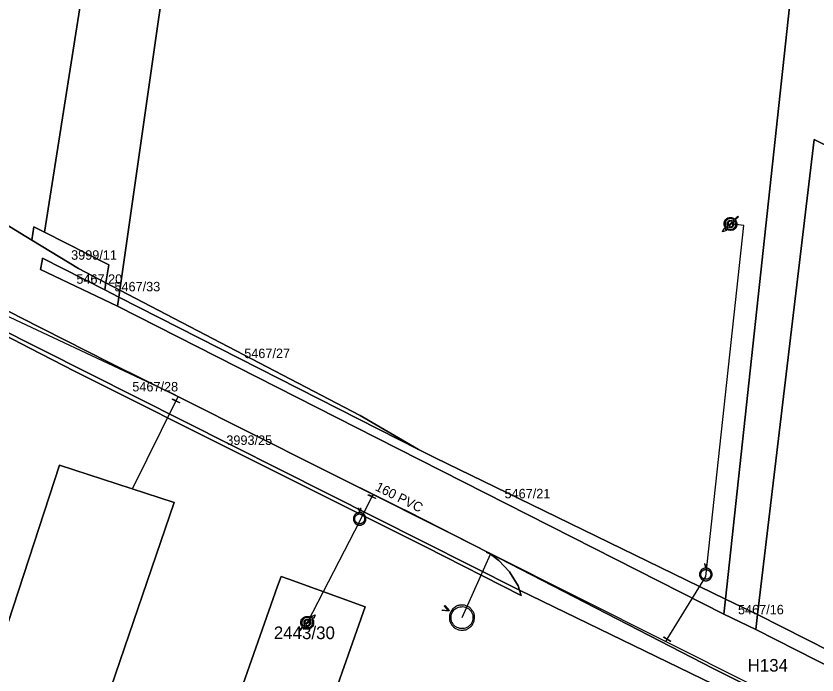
# Model space of a CAD drawing. Extents: x -570104 to -569328, y -1087857 to -1087418.
# Drawn here: x -569658.3 to -569531.5, y -1087675.5 to -1087571.3 of the extents above; entities that cross this region are included whole.
import ezdxf

# ---------------------------------------------------------------- set-up
doc = ezdxf.new("R2010")
doc.units = 0
for name, color, linetype in [('Adresní místo-text', 7, 'Continuous'), ('Armatura vodovodní', 7, 'Continuous'), ('Default', 7, 'Continuous'), ('Odběrné místo', 7, 'Continuous'), ('Označení hydrantu', 7, 'Continuous'), ('Parcela-polygon', 7, 'Continuous'), ('Parcela-text', 7, 'Continuous'), ('Vodovodní přípojka', 7, 'Continuous'), ('Vodovodní řad', 7, 'Continuous'), ('Vodovodní šachta', 7, 'Continuous'), ('Řad vodovodní popis', 7, 'Continuous')]:
    doc.layers.add(name, color=color, linetype=linetype)

msp = doc.modelspace()

# ---------------------------------------------------------------- linework, layer by layer
at = {"layer": 'Armatura vodovodní'}
for points in [[(-569632.42, -1087632.5), (-569633.54, -1087631.94), (-569633.51, -1087631.87), (-569632.39, -1087632.43), (-569632.42, -1087632.5)], [(-569601.42, -1087647.63), (-569602.54, -1087647.07), (-569602.51, -1087647), (-569601.39, -1087647.56), (-569601.42, -1087647.63)], [(-569583.78, -1087656.11), (-569582.64, -1087656.62), (-569582.67, -1087656.69), (-569583.81, -1087656.18), (-569583.78, -1087656.11)], [(-569555.75, -1087669.51), (-569554.69, -1087670.17), (-569554.73, -1087670.24), (-569555.79, -1087669.58), (-569555.75, -1087669.51)]]:
    msp.add_lwpolyline(points, dxfattribs=at)
at = {"layer": 'Default'}
for points, degree in [([(-569545.98, -1087604.85), (-569546.23, -1087604.57), (-569546.23, -1087604.19), (-569546.23, -1087603.77), (-569545.94, -1087603.48), (-569545.64, -1087603.18), (-569545.22, -1087603.18), (-569544.84, -1087603.18), (-569544.56, -1087603.43)], 3), ([(-569544.68, -1087603.55), (-569544.91, -1087603.35), (-569545.22, -1087603.35), (-569545.57, -1087603.35), (-569545.82, -1087603.6), (-569546.07, -1087603.84), (-569546.07, -1087604.19), (-569546.07, -1087604.5), (-569545.86, -1087604.73)], 3), ([(-569544.46, -1087603.54), (-569544.22, -1087603.81), (-569544.22, -1087604.19), (-569544.22, -1087604.61), (-569544.51, -1087604.9), (-569544.81, -1087605.2), (-569545.22, -1087605.2), (-569545.6, -1087605.2), (-569545.88, -1087604.96)], 3), ([(-569545.76, -1087604.84), (-569545.53, -1087605.03), (-569545.22, -1087605.03), (-569544.88, -1087605.03), (-569544.63, -1087604.78), (-569544.38, -1087604.54), (-569544.38, -1087604.19), (-569544.38, -1087603.88), (-569544.58, -1087603.66)], 3), ([(-569545.66, -1087604.52), (-569545.67, -1087604.5), (-569545.68, -1087604.48), (-569545.74, -1087604.35), (-569545.74, -1087604.19), (-569545.74, -1087604.03), (-569545.68, -1087603.9), (-569545.61, -1087603.77), (-569545.49, -1087603.7), (-569545.37, -1087603.63), (-569545.23, -1087603.63), (-569545.08, -1087603.63), (-569544.96, -1087603.71), (-569544.92, -1087603.73), (-569544.89, -1087603.76)], 3), ([(-569544.98, -1087603.85), (-569545.08, -1087603.76), (-569545.23, -1087603.76), (-569545.39, -1087603.76), (-569545.49, -1087603.87), (-569545.6, -1087603.98), (-569545.6, -1087604.19), (-569545.6, -1087604.32), (-569545.55, -1087604.42), (-569545.55, -1087604.42), (-569545.55, -1087604.42)], 3), ([(-569544.79, -1087603.88), (-569544.79, -1087603.89), (-569544.78, -1087603.91), (-569544.72, -1087604.04), (-569544.72, -1087604.18), (-569544.72, -1087604.44), (-569544.86, -1087604.6), (-569545, -1087604.75), (-569545.23, -1087604.75), (-569545.38, -1087604.75), (-569545.5, -1087604.68), (-569545.53, -1087604.66), (-569545.55, -1087604.64)], 3), ([(-569545.46, -1087604.54), (-569545.44, -1087604.56), (-569545.42, -1087604.57), (-569545.34, -1087604.62), (-569545.23, -1087604.62), (-569545.08, -1087604.62), (-569544.97, -1087604.52), (-569544.86, -1087604.42), (-569544.86, -1087604.17), (-569544.86, -1087604.06), (-569544.9, -1087603.98)], 3), ([(-569604.76, -1087650.34), (-569604.84, -1087650.5), (-569604.89, -1087650.66), (-569604.89, -1087650.84)], 2), ([(-569604.39, -1087649.97), (-569604.54, -1087650.06), (-569604.67, -1087650.18), (-569604.76, -1087650.34)], 2), ([(-569604.68, -1087650.84), (-569604.68, -1087650.7), (-569604.65, -1087650.57), (-569604.57, -1087650.44)], 2), ([(-569604.57, -1087650.44), (-569604.5, -1087650.32), (-569604.41, -1087650.22), (-569604.28, -1087650.15)], 2), ([(-569603.9, -1087649.84), (-569604.07, -1087649.84), (-569604.23, -1087649.89), (-569604.39, -1087649.97)], 2), ([(-569604.28, -1087650.15), (-569604.16, -1087650.09), (-569604.03, -1087650.05), (-569603.9, -1087650.05)], 2), ([(-569603.89, -1087649.57), (-569603.89, -1087649.55), (-569603.9, -1087649.54), (-569603.9, -1087649.53)], 2), ([(-569603.41, -1087649.97), (-569603.57, -1087649.89), (-569603.73, -1087649.84), (-569603.9, -1087649.84)], 2), ([(-569603.9, -1087650.05), (-569603.77, -1087650.05), (-569603.64, -1087650.09), (-569603.52, -1087650.15)], 2), ([(-569603.88, -1087649.53), (-569603.88, -1087649.54), (-569603.89, -1087649.55), (-569603.89, -1087649.57)], 2), ([(-569603.52, -1087650.15), (-569603.39, -1087650.22), (-569603.3, -1087650.32), (-569603.22, -1087650.44)], 2), ([(-569603.04, -1087650.34), (-569603.13, -1087650.18), (-569603.26, -1087650.06), (-569603.41, -1087649.97)], 2), ([(-569603.22, -1087650.44), (-569603.15, -1087650.57), (-569603.12, -1087650.7), (-569603.12, -1087650.84)], 2), ([(-569602.91, -1087650.84), (-569602.91, -1087650.66), (-569602.95, -1087650.5), (-569603.04, -1087650.34)], 2), ([(-569604.89, -1087650.84), (-569604.89, -1087651.01), (-569604.85, -1087651.17), (-569604.76, -1087651.33)], 2), ([(-569604.76, -1087651.33), (-569604.67, -1087651.48), (-569604.55, -1087651.6), (-569604.39, -1087651.69)], 2), ([(-569604.58, -1087651.22), (-569604.65, -1087651.1), (-569604.68, -1087650.97), (-569604.68, -1087650.84)], 2), ([(-569604.29, -1087651.51), (-569604.41, -1087651.44), (-569604.51, -1087651.34), (-569604.58, -1087651.22)], 2), ([(-569604.39, -1087651.69), (-569604.23, -1087651.78), (-569604.07, -1087651.82), (-569603.9, -1087651.82)], 2), ([(-569603.9, -1087651.61), (-569604.04, -1087651.61), (-569604.16, -1087651.58), (-569604.29, -1087651.51)], 2), ([(-569603.51, -1087651.51), (-569603.63, -1087651.58), (-569603.76, -1087651.61), (-569603.9, -1087651.61)], 2), ([(-569603.9, -1087651.82), (-569603.73, -1087651.82), (-569603.56, -1087651.78), (-569603.41, -1087651.69)], 2), ([(-569603.22, -1087651.22), (-569603.29, -1087651.34), (-569603.39, -1087651.44), (-569603.51, -1087651.51)], 2), ([(-569603.41, -1087651.69), (-569603.25, -1087651.6), (-569603.13, -1087651.48), (-569603.04, -1087651.33)], 2), ([(-569603.12, -1087650.84), (-569603.12, -1087650.97), (-569603.15, -1087651.1), (-569603.22, -1087651.22)], 2), ([(-569603.04, -1087651.33), (-569602.95, -1087651.17), (-569602.91, -1087651.01), (-569602.91, -1087650.84)], 2), ([(-569549.99, -1087659.13), (-569550.08, -1087659.29), (-569550.12, -1087659.45), (-569550.12, -1087659.63)], 2), ([(-569549.62, -1087658.76), (-569549.78, -1087658.85), (-569549.9, -1087658.97), (-569549.99, -1087659.13)], 2), ([(-569549.91, -1087659.63), (-569549.91, -1087659.49), (-569549.88, -1087659.36), (-569549.81, -1087659.23)], 2), ([(-569549.81, -1087659.23), (-569549.74, -1087659.11), (-569549.64, -1087659.01), (-569549.51, -1087658.95)], 2), ([(-569549.13, -1087658.64), (-569549.3, -1087658.64), (-569549.46, -1087658.68), (-569549.62, -1087658.76)], 2), ([(-569549.51, -1087658.95), (-569549.39, -1087658.88), (-569549.26, -1087658.84), (-569549.13, -1087658.84)], 2), ([(-569549.12, -1087658.36), (-569549.13, -1087658.34), (-569549.13, -1087658.33), (-569549.13, -1087658.33)], 2), ([(-569548.65, -1087658.76), (-569548.8, -1087658.68), (-569548.97, -1087658.64), (-569549.13, -1087658.64)], 2), ([(-569549.13, -1087658.84), (-569549, -1087658.84), (-569548.87, -1087658.88), (-569548.75, -1087658.95)], 2), ([(-569549.11, -1087658.33), (-569549.11, -1087658.33), (-569549.12, -1087658.35), (-569549.12, -1087658.36)], 2), ([(-569548.75, -1087658.95), (-569548.62, -1087659.01), (-569548.53, -1087659.11), (-569548.46, -1087659.23)], 2), ([(-569548.28, -1087659.13), (-569548.36, -1087658.97), (-569548.49, -1087658.85), (-569548.65, -1087658.76)], 2), ([(-569548.46, -1087659.23), (-569548.39, -1087659.36), (-569548.35, -1087659.49), (-569548.35, -1087659.63)], 2), ([(-569548.14, -1087659.63), (-569548.14, -1087659.45), (-569548.19, -1087659.29), (-569548.28, -1087659.13)], 2), ([(-569550.12, -1087659.63), (-569550.12, -1087659.8), (-569550.08, -1087659.96), (-569549.99, -1087660.12)], 2), ([(-569549.99, -1087660.12), (-569549.9, -1087660.27), (-569549.78, -1087660.4), (-569549.62, -1087660.48)], 2), ([(-569549.81, -1087660.01), (-569549.88, -1087659.89), (-569549.91, -1087659.76), (-569549.91, -1087659.63)], 2), ([(-569549.52, -1087660.3), (-569549.64, -1087660.23), (-569549.74, -1087660.14), (-569549.81, -1087660.01)], 2), ([(-569549.62, -1087660.48), (-569549.46, -1087660.57), (-569549.3, -1087660.62), (-569549.13, -1087660.62)], 2), ([(-569549.13, -1087660.4), (-569549.27, -1087660.4), (-569549.4, -1087660.37), (-569549.52, -1087660.3)], 2), ([(-569548.74, -1087660.3), (-569548.87, -1087660.37), (-569549, -1087660.4), (-569549.13, -1087660.4)], 2), ([(-569549.13, -1087660.62), (-569548.96, -1087660.62), (-569548.79, -1087660.57), (-569548.64, -1087660.48)], 2), ([(-569548.45, -1087660.01), (-569548.52, -1087660.14), (-569548.62, -1087660.23), (-569548.74, -1087660.3)], 2), ([(-569548.64, -1087660.48), (-569548.48, -1087660.4), (-569548.36, -1087660.27), (-569548.27, -1087660.12)], 2), ([(-569548.35, -1087659.63), (-569548.35, -1087659.76), (-569548.39, -1087659.89), (-569548.45, -1087660.01)], 2), ([(-569548.27, -1087660.12), (-569548.19, -1087659.96), (-569548.14, -1087659.8), (-569548.14, -1087659.63)], 2), ([(-569589.48, -1087665.56), (-569589.25, -1087665.12), (-569588.81, -1087664.81), (-569588.37, -1087664.5), (-569587.83, -1087664.48), (-569587.28, -1087664.46), (-569586.82, -1087664.69), (-569586.36, -1087664.92), (-569586.06, -1087665.37), (-569585.76, -1087665.81), (-569585.74, -1087666.35), (-569585.72, -1087666.89), (-569585.95, -1087667.35), (-569586.18, -1087667.81), (-569586.63, -1087668.11), (-569587.07, -1087668.41), (-569587.61, -1087668.43), (-569588.15, -1087668.45), (-569588.6, -1087668.22), (-569589.07, -1087667.99), (-569589.37, -1087667.53), (-569589.68, -1087667.08), (-569589.69, -1087666.55), (-569589.71, -1087666.01), (-569589.48, -1087665.56)], 3), ([(-569590.04, -1087665.32), (-569589.94, -1087665.33), (-569589.87, -1087665.34), (-569589.93, -1087665.29), (-569589.99, -1087665.22)], 3), ([(-569589.26, -1087665.67), (-569589.46, -1087666.06), (-569589.44, -1087666.53), (-569589.43, -1087667), (-569589.17, -1087667.4), (-569588.9, -1087667.8), (-569588.49, -1087668), (-569588.09, -1087668.2), (-569587.62, -1087668.19), (-569587.15, -1087668.17), (-569586.76, -1087667.9), (-569586.37, -1087667.64), (-569586.17, -1087667.24), (-569585.96, -1087666.83), (-569585.98, -1087666.36), (-569586, -1087665.89), (-569586.26, -1087665.5), (-569586.53, -1087665.11), (-569586.93, -1087664.91), (-569587.33, -1087664.7), (-569587.81, -1087664.73), (-569588.29, -1087664.75), (-569588.68, -1087665.02), (-569589.06, -1087665.28), (-569589.26, -1087665.67)], 3), ([(-569612.97, -1087667.93), (-569613.21, -1087667.65), (-569613.21, -1087667.28), (-569613.21, -1087666.86), (-569612.92, -1087666.57), (-569612.62, -1087666.27), (-569612.2, -1087666.27), (-569611.83, -1087666.27), (-569611.55, -1087666.51)], 3), ([(-569611.67, -1087666.63), (-569611.9, -1087666.44), (-569612.2, -1087666.44), (-569612.55, -1087666.44), (-569612.8, -1087666.69), (-569613.04, -1087666.93), (-569613.04, -1087667.28), (-569613.04, -1087667.59), (-569612.85, -1087667.81)], 3), ([(-569611.44, -1087666.61), (-569611.19, -1087666.9), (-569611.19, -1087667.28), (-569611.19, -1087667.7), (-569611.49, -1087667.99), (-569611.79, -1087668.29), (-569612.2, -1087668.29), (-569612.59, -1087668.29), (-569612.87, -1087668.04)], 3), ([(-569612.75, -1087667.92), (-569612.52, -1087668.12), (-569612.2, -1087668.12), (-569611.86, -1087668.12), (-569611.61, -1087667.87), (-569611.36, -1087667.63), (-569611.36, -1087667.28), (-569611.36, -1087666.97), (-569611.56, -1087666.73)], 3), ([(-569612.63, -1087667.59), (-569612.64, -1087667.58), (-569612.65, -1087667.56), (-569612.71, -1087667.43), (-569612.71, -1087667.29), (-569612.71, -1087667.02), (-569612.57, -1087666.87), (-569612.42, -1087666.72), (-569612.2, -1087666.72), (-569612.05, -1087666.72), (-569611.93, -1087666.79), (-569611.9, -1087666.81), (-569611.87, -1087666.83)], 3), ([(-569611.97, -1087666.92), (-569611.98, -1087666.91), (-569612, -1087666.9), (-569612.09, -1087666.84), (-569612.2, -1087666.84), (-569612.35, -1087666.84), (-569612.46, -1087666.95), (-569612.56, -1087667.05), (-569612.56, -1087667.29), (-569612.56, -1087667.4), (-569612.53, -1087667.49)], 3), ([(-569611.77, -1087666.94), (-569611.76, -1087666.97), (-569611.75, -1087666.99), (-569611.68, -1087667.12), (-569611.68, -1087667.28), (-569611.68, -1087667.44), (-569611.75, -1087667.57), (-569611.81, -1087667.7), (-569611.94, -1087667.77), (-569612.06, -1087667.83), (-569612.2, -1087667.83), (-569612.35, -1087667.83), (-569612.47, -1087667.76), (-569612.5, -1087667.74), (-569612.54, -1087667.71)], 3), ([(-569612.44, -1087667.62), (-569612.34, -1087667.71), (-569612.2, -1087667.71), (-569612.04, -1087667.71), (-569611.93, -1087667.6), (-569611.83, -1087667.49), (-569611.83, -1087667.28), (-569611.83, -1087667.15), (-569611.87, -1087667.05), (-569611.87, -1087667.05), (-569611.87, -1087667.05)], 3)]:
    msp.add_open_spline(points, degree=degree, dxfattribs=at)
at = {"layer": 'Odběrné místo'}
for points in [[(-569544.89, -1087603.76), (-569544.68, -1087603.55)], [(-569544.58, -1087603.66), (-569544.79, -1087603.88)], [(-569544.56, -1087603.43), (-569544.07, -1087602.94), (-569543.97, -1087603.05), (-569544.46, -1087603.54)], [(-569546, -1087605.09), (-569545.88, -1087605.2), (-569546.47, -1087605.44), (-569546.25, -1087604.85), (-569546.11, -1087604.98), (-569545.98, -1087604.85)], [(-569545.88, -1087604.96), (-569546, -1087605.09)], [(-569545.86, -1087604.73), (-569545.66, -1087604.52)], [(-569545.55, -1087604.64), (-569545.76, -1087604.84)], [(-569545.55, -1087604.42), (-569544.98, -1087603.85)], [(-569544.9, -1087603.98), (-569545.46, -1087604.54)], [(-569612.53, -1087667.49), (-569611.97, -1087666.92)], [(-569611.87, -1087667.05), (-569612.44, -1087667.62)], [(-569611.87, -1087666.83), (-569611.67, -1087666.63)], [(-569611.56, -1087666.73), (-569611.77, -1087666.94)], [(-569611.55, -1087666.51), (-569611.42, -1087666.38)], [(-569611.42, -1087666.38), (-569611.54, -1087666.27), (-569610.96, -1087666.03), (-569611.18, -1087666.61), (-569611.31, -1087666.49), (-569611.44, -1087666.61)], [(-569612.87, -1087668.04), (-569613.35, -1087668.53), (-569613.46, -1087668.42), (-569612.97, -1087667.93)], [(-569612.85, -1087667.81), (-569612.63, -1087667.59)], [(-569612.54, -1087667.71), (-569612.75, -1087667.92)]]:
    msp.add_lwpolyline(points, dxfattribs=at)
at = {"layer": 'Parcela-polygon'}
for points in [[(-569657.69, -1087488.2), (-569659, -1087493.2), (-569684.16, -1087553.44), (-569688.63, -1087564.12), (-569686.23, -1087572.99), (-569680.91, -1087587.07), (-569672.82, -1087596.37), (-569655.79, -1087606.73), (-569655.45, -1087604.65), (-569653.75, -1087605.49), (-569636.87, -1087498.32), (-569636.55, -1087495.89)], [(-569636.55, -1087495.89), (-569636.87, -1087498.32), (-569653.75, -1087605.49), (-569643.58, -1087610.64), (-569644.05, -1087613.5), (-569641.87, -1087614.64), (-569629.33, -1087527.19), (-569625.65, -1087499.86)], [(-569625.65, -1087499.86), (-569629.33, -1087527.19), (-569641.87, -1087614.64), (-569603.81, -1087634.48), (-569594.58, -1087639.86), (-569591.97, -1087641.18), (-569576.77, -1087648.59), (-569546.02, -1087663.53), (-569532.21, -1087535.63), (-569559, -1087524.1)], [(-569559, -1087524.1), (-569532.21, -1087535.63), (-569546.02, -1087663.53), (-569540.95, -1087665.98), (-569531.99, -1087590.85), (-569361.55, -1087675.44)], [(-569361.55, -1087675.44), (-569531.99, -1087590.85), (-569540.95, -1087665.98), (-569475.81, -1087698.97), (-569405.39, -1087733.98), (-569385.57, -1087743.95), (-569327.71, -1087773.61)], [(-569327.71, -1087776.81), (-569541.23, -1087668.35), (-569546.28, -1087665.91), (-569601.25, -1087638), (-569642.24, -1087617.19), (-569654.41, -1087611.38), (-569654.16, -1087610.04), (-569654.08, -1087609.62), (-569644.23, -1087614.63), (-569644.05, -1087613.5), (-569648.37, -1087611.25), (-569655.79, -1087606.73), (-569672.82, -1087596.37)], [(-569668.31, -1087613.41), (-569657.69, -1087618.95), (-569643.42, -1087626.13), (-569631.73, -1087631.98), (-569610.29, -1087642.72), (-569597.52, -1087649.08), (-569596.28, -1087649.69), (-569583.46, -1087656.2), (-569547.98, -1087674.52), (-569517.48, -1087689.67)], [(-569538.96, -1087681.38), (-569578.63, -1087662.1), (-569578.36, -1087662.97), (-569593.51, -1087655.25), (-569621.66, -1087641.16), (-569649.02, -1087627.48), (-569656.08, -1087623.85), (-569670.86, -1087616.21)], [(-569674.15, -1087711.83), (-569651.41, -1087642.32), (-569633.25, -1087648.27), (-569643.94, -1087679.59), (-569636.12, -1087682.33), (-569634.05, -1087683.06), (-569635, -1087686.54), (-569636.91, -1087686.03), (-569640.33, -1087695.74), (-569648.38, -1087693.02), (-569656.5, -1087717.61), (-569674.15, -1087711.83)], [(-569635.37, -1087714.02), (-569616.89, -1087661.48), (-569616.35, -1087659.96), (-569615.13, -1087660.4), (-569603.05, -1087664.75), (-569623.04, -1087721.56), (-569627.3, -1087733.45), (-569639.21, -1087729.26), (-569635.07, -1087717.06), (-569639.81, -1087717), (-569642.81, -1087726.03), (-569647.65, -1087724.43), (-569643.27, -1087711.24), (-569635.37, -1087714.02)], [(-569327.71, -1087773.61), (-569385.57, -1087743.95), (-569405.39, -1087733.98), (-569475.81, -1087698.97), (-569540.95, -1087665.98), (-569541.23, -1087668.35), (-569327.71, -1087776.81)]]:
    msp.add_lwpolyline(points, dxfattribs=at)
for points in [[(-569655.79, -1087606.73), (-569648.37, -1087611.25), (-569644.05, -1087613.5), (-569643.58, -1087610.64), (-569653.75, -1087605.49), (-569655.45, -1087604.65)], [(-569578.74, -1087662.05), (-569578.63, -1087662.1), (-569578.84, -1087661.42), (-569580.22, -1087659.19), (-569581.88, -1087657.43), (-569583.46, -1087656.2), (-569596.28, -1087649.69), (-569597.52, -1087649.08), (-569610.29, -1087642.72), (-569631.73, -1087631.98), (-569643.42, -1087626.13), (-569657.69, -1087618.95), (-569668.31, -1087613.41), (-569677.05, -1087608.51), (-569683, -1087605.22), (-569683, -1087606.78), (-569683, -1087608), (-569688.74, -1087606.97), (-569677.4, -1087612.64), (-569676.9, -1087612.89), (-569661.94, -1087620.21)], [(-569642.24, -1087617.19), (-569642.03, -1087615.78), (-569644.23, -1087614.63), (-569654.08, -1087609.62), (-569654.16, -1087610.04), (-569654.41, -1087611.38)], [(-569578.74, -1087662.05), (-569661.94, -1087620.21), (-569676.9, -1087612.89), (-569670.86, -1087616.21), (-569656.08, -1087623.85), (-569649.02, -1087627.48), (-569621.66, -1087641.16), (-569593.51, -1087655.25), (-569578.36, -1087662.97), (-569578.63, -1087662.1)], [(-569641.87, -1087614.64), (-569644.05, -1087613.5), (-569644.23, -1087614.63), (-569642.03, -1087615.78)], [(-569594.58, -1087639.86), (-569603.81, -1087634.48), (-569641.87, -1087614.64), (-569642.03, -1087615.78)], [(-569642.24, -1087617.19), (-569601.25, -1087638), (-569546.28, -1087665.91), (-569546.02, -1087663.53), (-569576.77, -1087648.59), (-569591.97, -1087641.18), (-569594.58, -1087639.86), (-569642.03, -1087615.78)], [(-569674.15, -1087711.83), (-569656.5, -1087717.61), (-569648.38, -1087693.02), (-569640.33, -1087695.74), (-569636.91, -1087686.03), (-569635, -1087686.54), (-569634.05, -1087683.06), (-569636.12, -1087682.33), (-569643.94, -1087679.59), (-569633.25, -1087648.27), (-569651.41, -1087642.32)], [(-569538.96, -1087681.38), (-569481.19, -1087711.33), (-569480.67, -1087711.59), (-569481.46, -1087710.69), (-569482.62, -1087709.76), (-569487.65, -1087706.59), (-569517.48, -1087689.67), (-569547.98, -1087674.52), (-569583.46, -1087656.2), (-569581.88, -1087657.43), (-569580.22, -1087659.19), (-569578.84, -1087661.42), (-569578.63, -1087662.1)], [(-569635.07, -1087717.06), (-569623.04, -1087721.56), (-569603.05, -1087664.75), (-569615.13, -1087660.4), (-569616.35, -1087659.96), (-569616.89, -1087661.48), (-569635.37, -1087714.02), (-569635.87, -1087715.43), (-569636.29, -1087716.6)], [(-569546.28, -1087665.91), (-569541.23, -1087668.35), (-569540.95, -1087665.98), (-569546.02, -1087663.53)]]:
    msp.add_lwpolyline(points, close=True, dxfattribs=at)
at = {"layer": 'Vodovodní přípojka'}
for points in [[(-569555.45, -1087670.22), (-569555.24, -1087669.88), (-569549.13, -1087659.96), (-569543.12, -1087604.44), (-569545.22, -1087604.19)], [(-569632.62, -1087631.48), (-569632.97, -1087632.19), (-569639.9, -1087646.16)], [(-569601.79, -1087646.96), (-569601.97, -1087647.31), (-569603.9, -1087651.17), (-569612.21, -1087667.28)], [(-569587.71, -1087666.45), (-569583.22, -1087656.4), (-569583.18, -1087656.3)]]:
    msp.add_lwpolyline(points, dxfattribs=at)
at = {"layer": 'Vodovodní řad'}
msp.add_lwpolyline([(-569704.52, -1087621.35), (-569688.87, -1087604.08), (-569665.83, -1087615.89), (-569665.36, -1087616.11), (-569633.42, -1087631.08), (-569632.62, -1087631.48), (-569601.79, -1087646.96), (-569583.18, -1087656.3), (-569555.45, -1087670.22), (-569542.09, -1087676.92), (-569540.21, -1087677.85)], dxfattribs=at)
at = {"layer": 'Vodovodní šachta'}
for points in [[(-569603.9, -1087649.53), (-569604.02, -1087649.17), (-569604.12, -1087649.17), (-569603.93, -1087649.68)], [(-569603.93, -1087649.68), (-569603.86, -1087649.68), (-569603.66, -1087649.17), (-569603.75, -1087649.17), (-569603.88, -1087649.53)], [(-569549.13, -1087658.33), (-569549.26, -1087657.97), (-569549.35, -1087657.97), (-569549.16, -1087658.47)], [(-569549.16, -1087658.47), (-569549.09, -1087658.47), (-569548.89, -1087657.97), (-569548.98, -1087657.97), (-569549.11, -1087658.33)], [(-569589.99, -1087665.22), (-569590.52, -1087664.65), (-569590.45, -1087664.53), (-569589.74, -1087665.33), (-569589.8, -1087665.46)], [(-569589.8, -1087665.46), (-569590.87, -1087665.35), (-569590.81, -1087665.22), (-569590.04, -1087665.32)]]:
    msp.add_lwpolyline(points, dxfattribs=at)

# ---------------------------------------------------------------- texts
at = {"layer": 'Adresní místo-text'}
msp.add_text('2443/30', height=2, dxfattribs=at).set_placement((-569617.49, -1087669.86))
at = {"layer": 'Označení hydrantu'}
msp.add_text('H134', height=2, dxfattribs=at).set_placement((-569542.52, -1087675))
at = {"layer": 'Parcela-text'}
for s, p in [('3999/11', (-569649.56, -1087609.85)), ('5467/20', (-569648.73, -1087613.65)), ('5467/33', (-569642.71, -1087614.85)), ('5467/27', (-569622.17, -1087625.41)), ('5467/28', (-569639.88, -1087630.68)), ('3993/25', (-569625, -1087639.14)), ('5467/21', (-569580.98, -1087647.59)), ('5467/16', (-569544.04, -1087665.94))]:
    msp.add_text(s, height=1.5, dxfattribs=at).set_placement(p)
at = {"layer": 'Řad vodovodní popis'}
msp.add_text(' 160 PVC', height=1.5, rotation=333.3442, dxfattribs=at).set_placement((-569602.06, -1087646.01))

doc.saveas('drawing.dxf')
